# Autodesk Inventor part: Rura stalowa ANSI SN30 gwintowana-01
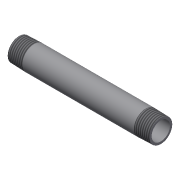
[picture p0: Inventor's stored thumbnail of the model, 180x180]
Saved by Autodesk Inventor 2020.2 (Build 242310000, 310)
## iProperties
Created: 2014-08
Part Number: Rura stalowa ANSI SN30 gwintowana-01
Material: Ogólny
Document SubType Name: Modeling
Designer: F.Stasiak
Density: 1 g/cm^3
Appearance: Domyślna
Categories: <MemberInstance><Categories><Category DisplayName="" InternalName="4347fa0f-2144-441d-94cd-e3e15c92b736" Mnemonic="TUBEANDPIPE"><CategoryParameter DisplayName="
Catalog Web Link: www.expertbooks.pl
Manager: www.cadconsulting.pl
Company: Fabian Stasiak CAD Consulting
Author: F.Stasiak
Subject: Zbiór ćwiczeń. Autodesk Inventor 2020. Kurs Professional
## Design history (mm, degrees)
sketch "Szkic1"
  geometry: L1 (0, 8.255)-(127, 8.255); L2 (127, 8.255)-(127, 10.247); L3 (0, 10.247)-(0, 8.255); L4 (0, 0)-(127, 0); L5 (0, 10.247)-(13.462, 10.668); L6 (13.462, 10.668)-(113.538, 10.668); L7 (113.538, 10.668)-(127, 10.247); L8 (0, 0)-(0, 8.255); L9 (127, 8.255)-(127, 0); L10 (13.462, 10.668)-(13.462, 0); L11 (113.538, 10.668)-(113.538, 0)
  constraints: 22 end point, 3 horizontal, 3 perpendicular, 2 equal length, 2 point on line, 2 vertical, 1 parallel
  dimensions: "d1" = 1.79 deg angle of L5 L6; "LG" = 13.462 distance between parallel lines of L10 L8; "ID" = 16.51 diameter of L1 L4; "OD" = 21.336 diameter of L6 L4; "PL" = 127 distance of L4.start L4.end
revolve "Obrót1" sketch "Szkic1" stored, may be unused: angle "d6" = 90 deg
feature "Gwint1" dims "d7" = 19.8628, "d8" = 0
feature "Gwint2" dims "d9" = 19.8628, "d10" = 0
node "Bryła1"
